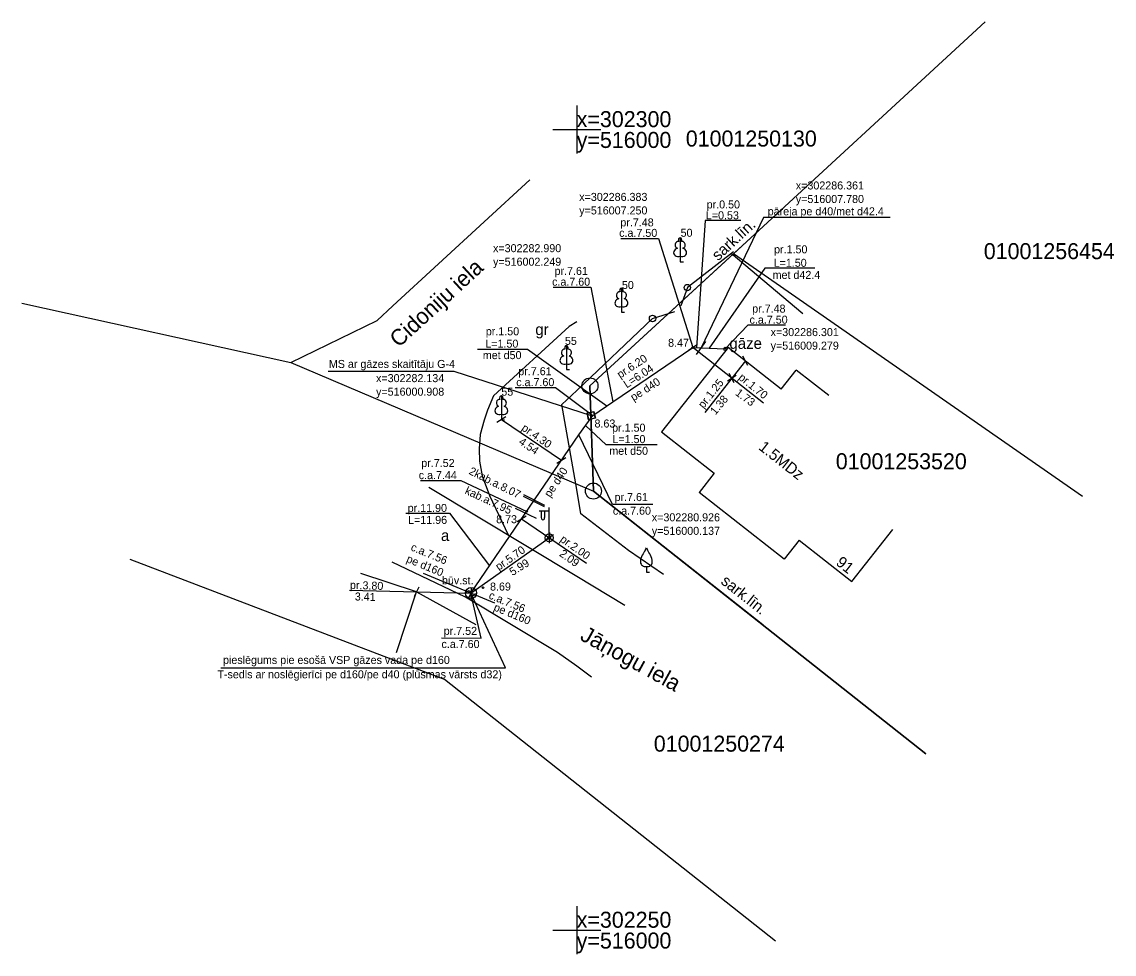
# Model space of a CAD drawing. Extents: x 515898 to 516108, y 302194 to 302343.
# Drawn here: x 515965.3 to 516033.6, y 302248.5 to 302306.7 of the extents above; entities that cross this region are included whole.
import ezdxf

# ---------------------------------------------------------------- set-up
doc = ezdxf.new("R2010")
doc.units = 0
for name, color, linetype in [('APGR_ELEM_####_####_#', 7, 'Continuous'), ('APGR_SARK_####_####_#', 7, 'Continuous'), ('APGR_SARK_####_TKST_#', 7, 'Continuous'), ('APGS_ELEM_####_####_#', 7, 'Continuous'), ('APGS_VADP_ZSPR_####_#', 7, 'Continuous'), ('APGS_VADP_ZSPR_TKST_#', 7, 'Continuous'), ('BUVE_EKAS_####_####_#', 7, 'Continuous'), ('BUVE_EKAS_ADRS_TKST_#', 7, 'Continuous'), ('BUVE_EKAS_RAKS_TKST_#', 7, 'Continuous'), ('CELI_CMAL_####_####_#', 7, 'Continuous'), ('CELI_CSEG_####_TKST_#', 7, 'Continuous'), ('CELI_IELA_####_TKST_#', 7, 'Continuous'), ('ELEK_VADP_ZSPR_####_#', 7, 'Continuous'), ('ELEK_VADP_ZSPR_TKST_#', 7, 'Continuous'), ('GAZE_ACRL_####_####_#', 7, 'Continuous'), ('GAZE_ACRL_####_TKST_#', 7, 'Continuous'), ('GAZE_ELEM_####_####_#', 7, 'Continuous'), ('GAZE_ELEM_####_TKST_#', 7, 'Continuous'), ('GAZE_VADP_VSP1_####_#', 7, 'Continuous'), ('GAZE_VADP_VSP1_####_I', 7, 'Continuous'), ('GAZE_VADP_VSP1_TKST_#', 7, 'Continuous'), ('GAZE_VADP_VSP1_TKST_I', 7, 'Continuous'), ('GAZE_VADP_ZSPD_####_I', 7, 'Continuous'), ('GAZE_VADP_ZSPD_TKST_I', 7, 'Continuous'), ('GEOD_ELEM_####_####_#', 7, 'Continuous'), ('GEOD_KORD_####_TKST_#', 7, 'Continuous'), ('NORB_ELEM_####_####_#', 7, 'Continuous'), ('NORB_ZOGS_BARJ_####_#', 7, 'Continuous'), ('NORB_ZOGS_ZSTP_####_#', 7, 'Continuous'), ('RAMI_IZPM_####_TKST_#', 7, 'Continuous'), ('RAMI_IZPM_BUVE_####_#', 7, 'Continuous'), ('RELJ_AATZ_####_TKST_#', 7, 'Continuous'), ('RELJ_ELEM_####_####_#', 7, 'Continuous'), ('ROBZ_PROJ_####_####_#', 7, 'Continuous'), ('ROBZ_PROJ_####_TKST_#', 7, 'Continuous'), ('ROBZ_UZMR_####_####_#', 7, 'Continuous'), ('ROBZ_UZMR_####_TKST_#', 7, 'Continuous'), ('TERT_DIAM_####_TKST_#', 7, 'Continuous'), ('TERT_ELEM_####_####_#', 7, 'Continuous')]:
    doc.layers.add(name, color=color, linetype=linetype)

msp = doc.modelspace()

# ---------------------------------------------------------------- linework, layer by layer
at = {"layer": 'APGR_ELEM_####_####_#'}
for centre in [(516000.829, 302283.992), (516001.043, 302277.423)]:
    msp.add_circle(centre, 0.5, dxfattribs=at)
at = {"layer": 'APGR_SARK_####_####_#'}
for p, q in [((516000.829, 302283.992), (516010.872, 302293.247)), ((516001.043, 302277.423), (516000.829, 302283.992)), ((516011.619, 302269.059), (516001.043, 302277.423))]:
    msp.add_line(p, q, dxfattribs=at)
at = {"layer": 'APGS_ELEM_####_####_#'}
for p, q in [((515998.284, 302274.503), (515998.284, 302276.385)), ((515998.284, 302276.169), (515997.649, 302276.164)), ((515997.784, 302276.165), (515997.784, 302275.773)), ((515997.994, 302276.167), (515997.994, 302275.773))]:
    msp.add_line(p, q, dxfattribs=at)
for radius in [0.25, 0.09]:
    msp.add_circle((515998.284, 302274.503), radius, dxfattribs=at)
msp.add_ellipse((515997.889, 302275.773), major_axis=(0, 0.151), ratio=0.695971, start_param=1.570796, end_param=4.712389, dxfattribs=at)
at = {"layer": 'APGS_VADP_ZSPR_####_#'}
msp.add_line((515996.152, 302276.347), (515997.467, 302275.731), dxfattribs=at)
at = {"layer": 'BUVE_EKAS_####_####_#'}
for p, q in [((516009.46, 302286.395), (516005.299, 302281.124)), ((516012.776, 302283.788), (516009.46, 302286.395)), ((516012.776, 302283.788), (516013.707, 302284.973)), ((516015.743, 302283.381), (516013.707, 302284.973)), ((516005.299, 302281.124), (516008.592, 302278.531)), ((516008.592, 302278.531), (516007.651, 302277.336)), ((516012.951, 302273.169), (516007.651, 302277.336)), ((516017.184, 302271.764), (516019.752, 302275.021)), ((516013.888, 302274.359), (516012.951, 302273.169)), ((516013.888, 302274.359), (516017.184, 302271.764))]:
    msp.add_line(p, q, dxfattribs=at)
at = {"layer": 'CELI_CMAL_####_####_#'}
for points in [[(516000.001, 302287.995), (515999.531, 302287.701), (515994.805, 302283.363), (515994.439, 302282.464), (515994.23, 302281.842), (515993.971, 302280.947), (515993.902, 302280.051), (515993.92, 302279.292), (515994.092, 302278.378), (515994.545, 302277.14), (515995.729, 302274.682)], [(515990.774, 302277.668), (516000.001, 302272.108)], [(516000.001, 302266.479), (515998.801, 302267.346), (515993.047, 302270.792), (515988.477, 302272.981)], [(515999.999, 302272.109), (516003.012, 302270.293)], [(516000.933, 302265.805), (515999.999, 302266.48)]]:
    msp.add_lwpolyline(points, dxfattribs=at)
at = {"layer": 'ELEK_VADP_ZSPR_####_#'}
for points in [[(515996.667, 302277.109), (515997.974, 302276.453)], [(515996.677, 302277.203), (515997.984, 302276.547)]]:
    msp.add_lwpolyline(points, dxfattribs=at)
at = {"layer": 'GAZE_ACRL_####_####_#'}
for points in [[(516001.007, 302282.148), (516002.249, 302282.99)], [(516000.137, 302280.926), (516001.007, 302282.148)]]:
    msp.add_lwpolyline(points, dxfattribs=at)
at = {"layer": 'GAZE_ACRL_####_TKST_#'}
for points in [[(515993.802, 302286.29), (515996.931, 302286.29), (516001.878, 302282.739)], [(516005.018, 302280.3), (516001.835, 302280.3), (516000.554, 302281.512)]]:
    msp.add_lwpolyline(points, dxfattribs=at)
at = {"layer": 'GAZE_ELEM_####_####_#'}
msp.add_line((516007.491, 302285.953), (516008.069, 302286.769), dxfattribs=at)
for points in [[(516000.742, 302281.869), (516000.645, 302282.305), (516001.075, 302282.4), (516001.171, 302281.964)], [(516000.759, 302281.896), (516000.673, 302282.287), (516001.057, 302282.372), (516001.144, 302281.981)]]:
    msp.add_lwpolyline(points, close=True, dxfattribs=at)
for centre, radius in [((516009.279, 302286.301), 0.1), ((515993.397, 302271.046), 0.35)]:
    msp.add_circle(centre, radius, dxfattribs=at)
for centre, start, end in [((515993.257, 302271.046), 0, 180), ((515993.537, 302271.046), 180, 0)]:
    msp.add_arc(centre, 0.14, start, end, dxfattribs=at)
at = {"layer": 'GAZE_VADP_VSP1_####_#'}
msp.add_line((515990.413, 302272.285), (515994.861, 302270.438), dxfattribs=at)
at = {"layer": 'GAZE_VADP_VSP1_####_I'}
for points in [[(516000.137, 302280.926), (516001.007, 302282.148)], [(515993.397, 302271.046), (516000.136, 302280.927)]]:
    msp.add_lwpolyline(points, dxfattribs=at)
at = {"layer": 'GAZE_VADP_VSP1_TKST_I'}
for points in [[(515996.151, 302283.885), (515998.671, 302283.885), (516001.007, 302282.148)], [(516004.746, 302276.587), (516002.226, 302276.587), (516000.137, 302280.926)], [(515990.252, 302278.078), (515992.772, 302278.078), (515996.877, 302276.149)], [(515991.554, 302268.248), (515994.037, 302268.238), (515993.397, 302271.046)]]:
    msp.add_lwpolyline(points, dxfattribs=at)
at = {"layer": 'GAZE_VADP_ZSPD_####_I'}
for points in [[(516002.249, 302282.99), (516007.25, 302286.383)], [(516007.25, 302286.383), (516007.78, 302286.361)], [(516007.78, 302286.361), (516009.279, 302286.301)], [(516001.007, 302282.148), (516002.249, 302282.99)]]:
    msp.add_lwpolyline(points, dxfattribs=at)
at = {"layer": 'GAZE_VADP_ZSPD_TKST_I'}
for points in [[(516002.751, 302293.199), (516005.102, 302293.199), (516007.25, 302286.383)], [(516014.875, 302291.347), (516011.746, 302291.347), (516008.264, 302286.342)], [(515998.534, 302290.149), (516000.885, 302290.149), (516002.249, 302282.99)], [(516013.041, 302287.777), (516010.691, 302287.777), (516009.279, 302286.301)]]:
    msp.add_lwpolyline(points, dxfattribs=at)
at = {"layer": 'GEOD_ELEM_####_####_#'}
for p, q in [((516000, 302301.5), (516000, 302300)), ((515998.5, 302300), (516000, 302300)), ((516000, 302300), (516000, 302298.5)), ((516000, 302300), (516001.5, 302300)), ((516000, 302251.5), (516000, 302250)), ((515998.5, 302250), (516000, 302250)), ((516000, 302250), (516000, 302248.5)), ((516000, 302250), (516001.5, 302250))]:
    msp.add_line(p, q, dxfattribs=at)
at = {"layer": 'NORB_ELEM_####_####_#'}
for centre in [(516006.91, 302290.129), (516004.74, 302288.201)]:
    msp.add_circle(centre, 0.202, dxfattribs=at)
at = {"layer": 'NORB_ZOGS_BARJ_####_#'}
for p, q in [((516006.91, 302290.129), (516006.505, 302288.981)), ((516004.74, 302288.201), (516006.125, 302288.628))]:
    msp.add_line(p, q, dxfattribs=at)
at = {"layer": 'NORB_ZOGS_ZSTP_####_#'}
for p, q in [((515988.746, 302267.348), (515989.992, 302271.125)), ((515989.992, 302271.125), (515993.698, 302269.079))]:
    msp.add_line(p, q, dxfattribs=at)
for points in [[(516009.784, 302292.371), (516006.91, 302290.129)], [(516014.119, 302288.49), (516009.644, 302292.262)], [(515999.999, 302283.711), (516004.74, 302288.201)], [(516000.001, 302277.516), (515999.067, 302282.828), (515999.999, 302283.711)], [(516000.268, 302275.997), (515999.999, 302277.527)], [(516005.423, 302272.213), (516003.237, 302273.701), (516000.268, 302275.997)], [(515989.992, 302271.125), (515986.524, 302272.27)]]:
    msp.add_lwpolyline(points, dxfattribs=at)
at = {"layer": 'RAMI_IZPM_####_TKST_#'}
for p, q in [((516007.526, 302286.561), (516006.974, 302286.204)), ((516011.669, 302282.908), (516007.25, 302286.383)), ((516010.534, 302285.55), (516007.997, 302282.323)), ((516010.691, 302285.262), (516010.377, 302285.839)), ((516009.96, 302284.647), (516009.408, 302284.291)), ((516009.841, 302284.181), (516009.527, 302284.757)), ((515995.569, 302282.057), (515995.018, 302281.701)), ((515999.042, 302279.323), (515995.294, 302281.879)), ((515999.318, 302279.501), (515998.766, 302279.145)), ((515996.834, 302275.858), (515996.282, 302275.502)), ((515996.558, 302275.68), (516000.612, 302272.915)), ((515993.397, 302271.046), (515998.284, 302274.503)), ((515998.56, 302274.681), (515998.009, 302274.324)), ((515998.294, 302274.831), (515998.274, 302274.174)), ((515985.807, 302271.222), (515993.397, 302271.046)), ((515990.142, 302271.417), (515989.842, 302270.833)), ((515993.548, 302271.338), (515993.247, 302270.754)), ((515993.407, 302271.374), (515993.388, 302270.717))]:
    msp.add_line(p, q, dxfattribs=at)
for points in [[(516010.249, 302294.312), (516008.014, 302294.312), (516007.474, 302286.374)], [(516019.57, 302294.506), (516011.669, 302294.506), (516007.78, 302286.361)], [(515984.477, 302284.902), (515992.337, 302284.902), (516000.908, 302282.134)], [(515989.327, 302276.045), (515992.065, 302276.045), (515994.561, 302272.751)], [(515977.782, 302266.387), (515995.558, 302266.387), (515993.397, 302271.046)]]:
    msp.add_lwpolyline(points, dxfattribs=at)
at = {"layer": 'RAMI_IZPM_BUVE_####_#'}
for points in [[(516002.249, 302282.99), (516007.25, 302286.383)], [(516007.25, 302286.383), (516007.78, 302286.361)], [(516007.78, 302286.361), (516009.279, 302286.301)], [(516001.007, 302282.148), (516002.249, 302282.99)], [(516000.137, 302280.926), (516001.007, 302282.148)], [(515993.397, 302271.046), (516000.136, 302280.927)]]:
    msp.add_lwpolyline(points, dxfattribs=at)
at = {"layer": 'RELJ_ELEM_####_####_#'}
for centre in [(516007.25, 302286.383), (515996.877, 302276.149), (515994.151, 302271.385)]:
    msp.add_circle(centre, 0.05, dxfattribs=at)
at = {"layer": 'ROBZ_PROJ_####_####_#'}
for p, q in [((516025.5, 302306.726), (516009.785, 302292.245)), ((515988.52, 302288.98), (515997.08, 302296.858)), ((516009.785, 302292.245), (516000.829, 302283.992)), ((515965.35, 302289.16), (515982.15, 302285.45)), ((515987.53, 302288.07), (515988.52, 302288.98)), ((515982.15, 302285.45), (515987.53, 302288.07)), ((515982.15, 302285.45), (516001.043, 302277.423)), ((516000.829, 302283.992), (516001.043, 302277.423)), ((516001.043, 302277.423), (516021.802, 302261.009)), ((515988.414, 302266.931), (515972.107, 302273.149)), ((515991.742, 302265.662), (515988.414, 302266.931)), ((516012.412, 302249.316), (515991.742, 302265.662))]:
    msp.add_line(p, q, dxfattribs=at)
at = {"layer": 'ROBZ_UZMR_####_####_#'}
for p, q in [((516009.785, 302292.245), (516025.5, 302306.726)), ((516000.829, 302283.992), (516009.785, 302292.245)), ((516031.594, 302277.08), (516009.785, 302292.245)), ((516001.043, 302277.423), (516000.829, 302283.992)), ((516021.802, 302261.009), (516001.043, 302277.423))]:
    msp.add_line(p, q, dxfattribs=at)
at = {"layer": 'TERT_ELEM_####_####_#'}
for p, q in [((516006.461, 302292.09), (516006.461, 302291.743)), ((516006.461, 302291.743), (516006.661, 302291.743)), ((516002.793, 302288.941), (516002.793, 302288.594)), ((516002.793, 302288.594), (516002.993, 302288.594)), ((515999.357, 302285.363), (515999.357, 302285.016)), ((515999.357, 302285.016), (515999.557, 302285.016)), ((515995.294, 302282.226), (515995.294, 302281.879)), ((515995.294, 302281.879), (515995.494, 302281.879)), ((516004.352, 302272.718), (516004.352, 302272.366)), ((516004.352, 302272.366), (516004.552, 302272.366))]:
    msp.add_line(p, q, dxfattribs=at)
for points in [[(516006.461, 302293.243), (516006.461, 302292.09)], [(516006.55, 302293.011), (516006.549, 302293.012)], [(516002.793, 302290.094), (516002.793, 302288.941)], [(516002.883, 302289.861), (516002.882, 302289.862)], [(515999.357, 302286.516), (515999.357, 302285.363)], [(515999.446, 302286.284), (515999.445, 302286.285)], [(515995.294, 302283.379), (515995.294, 302282.226)], [(515995.383, 302283.147), (515995.382, 302283.148)]]:
    msp.add_lwpolyline(points, dxfattribs=at)
for centre, radius, start, end in [((516016.977, 302265.97), 14.88, 148.48442, 149.99014), ((516003.935, 302274.004), 0.439, 324.38368, 341.71196), ((516004.769, 302274.004), 0.439, 198.28804, 215.61632), ((515991.727, 302265.97), 14.88, 30.00986, 31.51558), ((516004.876, 302272.991), 0.89, 151.75702, 179.91384), ((516004.275, 302272.998), 0.29, 181.07816, 285.2823), ((516004.428, 302272.998), 0.29, 254.7177, 358.92184), ((516003.827, 302272.991), 0.89, 0.08616, 28.24297)]:
    msp.add_arc(centre, radius, start, end, dxfattribs=at)
for centre, major_axis, ratio, start_param, end_param in [((516006.332, 302292.799), (-0.039, -0.212), 0.861323, 3.141593, 6.283185), ((516006.461, 302293.093), (0, -0.15), 0.707107, 3.14537, 5.287485), ((516006.46, 302293.093), (0, -0.15), 0.707107, 0.995701, 3.137816), ((516006.589, 302292.799), (0.039, -0.212), 0.861323, 0, 3.141593), ((516006.371, 302292.336), (0.307, 0.095), 0.814445, 1.570796, 4.752015), ((516006.55, 302292.336), (-0.307, 0.095), 0.814445, 1.531171, 4.712389), ((516002.794, 302289.944), (0, -0.15), 0.707107, 3.14537, 5.287485), ((516002.793, 302289.944), (0, -0.15), 0.707107, 0.995701, 3.137816), ((516002.704, 302289.187), (0.307, 0.095), 0.814445, 1.570796, 4.752015), ((516002.665, 302289.649), (-0.039, -0.212), 0.861323, 3.141593, 6.283185), ((516002.883, 302289.187), (-0.307, 0.095), 0.814445, 1.531171, 4.712389), ((516002.921, 302289.649), (0.039, -0.212), 0.861323, 0, 3.141593), ((515999.228, 302286.071), (-0.039, -0.212), 0.861323, 3.141593, 6.283185), ((515999.357, 302286.366), (0, -0.15), 0.707107, 3.14537, 5.287485), ((515999.356, 302286.366), (0, -0.15), 0.707107, 0.995701, 3.137816), ((515999.485, 302286.071), (0.039, -0.212), 0.861323, 0, 3.141593), ((515999.267, 302285.609), (0.307, 0.095), 0.814445, 1.570796, 4.752015), ((515999.446, 302285.609), (-0.307, 0.095), 0.814445, 1.531171, 4.712389), ((515995.165, 302282.934), (-0.039, -0.212), 0.861323, 3.141593, 6.283185), ((515995.294, 302283.229), (0, -0.15), 0.707107, 3.14537, 5.287485), ((515995.293, 302283.229), (0, -0.15), 0.707107, 0.995701, 3.137816), ((515995.422, 302282.934), (0.039, -0.212), 0.861323, 0, 3.141593), ((515995.204, 302282.472), (0.307, 0.095), 0.814445, 1.570796, 4.752015), ((515995.383, 302282.472), (-0.307, 0.095), 0.814445, 1.531171, 4.712389)]:
    msp.add_ellipse(centre, major_axis=major_axis, ratio=ratio, start_param=start_param, end_param=end_param, dxfattribs=at)

# ---------------------------------------------------------------- texts
at = {"layer": 'APGR_SARK_####_TKST_#'}
for rotation, p in [(42.66074, (516008.826, 302291.764)), (321.66201, (516008.953, 302271.686))]:
    msp.add_text('sark.līn.', height=0.7, rotation=rotation, dxfattribs=at).set_placement(p)
at = {"layer": 'APGS_VADP_ZSPR_TKST_#'}
msp.add_text('kab.a.7.95', height=0.5, rotation=334.88779, dxfattribs=at).set_placement((515992.976, 302277.279))
at = {"layer": 'BUVE_EKAS_ADRS_TKST_#'}
msp.add_text('91', height=0.7, rotation=321.77789, dxfattribs=at).set_placement((516016.137, 302272.856))
at = {"layer": 'BUVE_EKAS_RAKS_TKST_#'}
msp.add_text('1.5MDz', height=0.7, rotation=321.82596, dxfattribs=at).set_placement((516011.308, 302280.064))
at = {"layer": 'CELI_CSEG_####_TKST_#'}
for s, p in [('gr', (515997.418, 302287.165)), ('a', (515991.525, 302274.302))]:
    msp.add_text(s, height=0.7, dxfattribs=at).set_placement(p)
at = {"layer": 'CELI_IELA_####_TKST_#'}
for s, rotation, p in [('Cidoniju iela', 42.54885, (515988.886, 302286.347)), ('Jāņogu iela', 331.23342, (516000.144, 302268.161))]:
    msp.add_text(s, height=1, rotation=rotation, dxfattribs=at).set_placement(p)
at = {"layer": 'ELEK_VADP_ZSPR_TKST_#'}
msp.add_text('2kab.a.8.07', height=0.5, rotation=333.35472, dxfattribs=at).set_placement((515993.225, 302278.507))
at = {"layer": 'GAZE_ACRL_####_TKST_#'}
for p in [(515994.137, 302285.662), (516002.037, 302279.686)]:
    msp.add_text('met d50', height=0.5, dxfattribs=at).set_placement(p)
at = {"layer": 'GAZE_ELEM_####_####_#'}
msp.add_text(' gāze', height=0.7, dxfattribs=at).set_placement((516009.279, 302286.301))
at = {"layer": 'GAZE_ELEM_####_TKST_#'}
msp.add_text('būv.st.', height=0.5, dxfattribs=at).set_placement((515991.586, 302271.595))
at = {"layer": 'GAZE_VADP_VSP1_TKST_#'}
for s, p in [('c.a.7.56', (515989.595, 302273.735)), ('pe d160', (515989.321, 302273.002)), ('c.a.7.56', (515994.462, 302270.732)), ('pe d160', (515994.769, 302269.984))]:
    msp.add_text(s, height=0.5, rotation=337.45434, dxfattribs=at).set_placement(p)
at = {"layer": 'GAZE_VADP_VSP1_TKST_I'}
for s, p in [('c.a.7.60', (515996.225, 302283.973)), ('c.a.7.44', (515990.135, 302278.166)), ('c.a.7.60', (516002.259, 302275.946)), ('c.a.7.60', (515991.556, 302267.619))]:
    msp.add_text(s, height=0.5, dxfattribs=at).set_placement(p)
msp.add_text('pe d40', height=0.5, rotation=56.43035, dxfattribs=at).set_placement((515998.343, 302276.987))
at = {"layer": 'GAZE_VADP_ZSPD_TKST_I'}
for s, p in [('c.a.7.50', (516002.652, 302293.296)), ('c.a.7.60', (515998.461, 302290.246)), ('met d42.4', (516012.236, 302290.673)), ('c.a.7.50', (516010.795, 302287.875))]:
    msp.add_text(s, height=0.5, dxfattribs=at).set_placement(p)
msp.add_text('pe d40', height=0.5, rotation=32.55485, dxfattribs=at).set_placement((516003.551, 302283.017))
at = {"layer": 'GEOD_KORD_####_TKST_#'}
for s, p in [('x=302300', (516000, 302300.15)), ('y=516000', (516000, 302298.85)), ('x=302250', (516000, 302250.15)), ('y=516000', (516000, 302248.85))]:
    msp.add_text(s, height=1, dxfattribs=at).set_placement(p)
at = {"layer": 'RAMI_IZPM_####_TKST_#'}
for s, p in [('x=302286.361', (516013.683, 302296.258)), ('x=302286.383', (516000.158, 302295.543)), ('pr.0.50', (516008.116, 302295.073)), ('y=516007.780', (516013.683, 302295.413)), ('y=516007.250', (516000.158, 302294.699)), ('L=0.53', (516008.065, 302294.395)), ('pāreja pe d40/met d42.4', (516011.929, 302294.644)), ('pr.7.48', (516002.726, 302293.951)), ('x=302282.990', (515994.776, 302292.34)), ('pr.1.50', (516012.327, 302292.269)), ('y=516002.249', (515994.776, 302291.496)), ('pr.7.61', (515998.616, 302290.919)), ('L=1.50', (516012.298, 302291.429)), ('pr.7.48', (516010.958, 302288.568)), ('pr.1.50', (515994.324, 302287.15)), ('x=302286.301', (516012.111, 302287.1)), ('L=1.50', (515994.292, 302286.377)), ('y=516009.279', (516012.111, 302286.255)), ('MS ar gāzes skaitītāju G-4', (515984.524, 302285.111)), ('x=302282.134', (515987.47, 302284.224)), ('pr.7.61', (515996.353, 302284.657)), ('y=516000.908', (515987.47, 302283.379)), ('pr.1.50', (516002.212, 302281.129)), ('L=1.50', (516002.228, 302280.416)), ('pr.7.52', (515990.295, 302278.924)), ('pr.7.61', (516002.365, 302276.797)), ('pr.11.90', (515989.446, 302276.114)), ('L=11.96', (515989.471, 302275.371)), ('x=302280.926', (516004.691, 302275.533)), ('y=516000.137', (516004.691, 302274.688)), ('pr.7.52', (515991.695, 302268.439)), ('pieslēgums pie esošā VSP gāzes vada pe d160', (515977.914, 302266.625)), ('T-sedls ar noslēgierīci pe d160/pe d40 (plūsmas vārsts d32)', (515977.564, 302265.728))]:
    msp.add_text(s, height=0.5, dxfattribs=at).set_placement(p)
for s, rotation, p in [('pr.6.20', 33.04729, (516002.716, 302284.439)), ('L=6.04', 33.04729, (516003.124, 302283.827)), ('pr.1.70', 321.38159, (516010.056, 302284.433)), ('pr.1.25', 51.3225, (516007.918, 302282.546)), ('1.38', 50.39948, (516008.665, 302282.141)), ('1.73', 323.3361, (516009.86, 302283.461)), ('pr.4.30', 325.12553, (515996.508, 302281.255)), ('4.54', 325.95341, (515996.337, 302280.393)), ('pr.2.00', 324.93596, (515998.914, 302274.307)), ('pr.5.70', 35.09743, (515995.139, 302272.434)), ('2.09', 324.63168, (515998.874, 302273.407)), ('5.99', 31.99563, (515995.99, 302272.111)), ('pr.3.80', 358.03386, (515985.835, 302271.314)), ('3.41', 358.59747, (515986.137, 302270.591))]:
    msp.add_text(s, height=0.5, rotation=rotation, dxfattribs=at).set_placement(p)
at = {"layer": 'RELJ_AATZ_####_TKST_#'}
for s, p in [('8.47', (516005.707, 302286.433)), ('8.63', (516001.112, 302281.391)), ('8.73', (515994.971, 302275.414)), ('8.69', (515994.588, 302271.208))]:
    msp.add_text(s, height=0.5, dxfattribs=at).set_placement(p)
at = {"layer": 'ROBZ_PROJ_####_TKST_#'}
for s, p in [('01001250130', (516006.812, 302298.938)), ('01001250274', (516004.814, 302261.147))]:
    msp.add_text(s, height=1, dxfattribs=at).set_placement(p)
at = {"layer": 'ROBZ_UZMR_####_TKST_#'}
for s, p in [('01001256454', (516025.422, 302291.906)), ('01001253520', (516016.179, 302278.783))]:
    msp.add_text(s, height=1, dxfattribs=at).set_placement(p)
at = {"layer": 'TERT_DIAM_####_TKST_#'}
for s, p in [('50', (516006.49, 302293.304)), ('50', (516002.825, 302290.043)), ('55', (515999.265, 302286.552)), ('55', (515995.294, 302283.379))]:
    msp.add_text(s, height=0.5, dxfattribs=at).set_placement(p)

doc.saveas('drawing.dxf')
